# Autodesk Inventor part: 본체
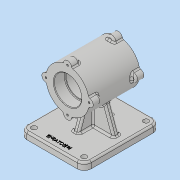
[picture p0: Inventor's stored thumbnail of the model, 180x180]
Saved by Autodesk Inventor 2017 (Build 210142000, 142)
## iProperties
Part Number: 본체
Material: 일반
Document SubType Name: Modeling
Designer: MRC
Density: 1 g/cm^3
Appearance: 기본값
Author: MRC
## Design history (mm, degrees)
sketch "스케치1"
  geometry: L1 (0, 0)-(0, 43.5); L2 (37, 43.5)-(23.5, 43.5); L3 (23.5, 43.5)-(23.5, 24.5); L4 (23.5, 24.5)-(21, 24.5); L5 (21, 24.5)-(21, 0); L6 (21, 0)-(37, 0); L7 (37, 0)-(37, 43.5)
  constraints: 14 end point, 5 perpendicular, 2 horizontal alignment, 1 horizontal, 1 vertical
  dimensions: "d0" = 43.5 distance of L1.start L1.end; "d1" = 47 diameter of L3 L1; "d2" = 42 diameter of L5 L1; "d3" = 74 diameter of L7 L1; "d4" = 19 distance of L2.end L3.end
revolve "회전1" sketch "스케치1" stored, may be unused: angle "d5" = 90 deg
sketch "스케치2"
  geometry: C1 r 7 at (0, 37); 2 further points
  constraints: 2 vertical alignment, 1 centre point, 1 other
  dimensions: "d6" = 14 diameter of C1
extrude "돌출1" join sketch "스케치2" distance "d7" = 14; taper "d8" = 0 deg
sketch "스케치3"
  geometry: A1 r 7 centre (0, 0) between (6.969, -0.662) and (-6.969, -0.662) reference; 2 further points
  constraints: 1 coincident
hole "구멍1" sketch "스케치3" at (0, 0) diameter "d9" = 3.242; stored, may be unused: countersink angle "d13" = 90 deg, drill point angle "d15" = 118 deg; dims "d10" = 8, "d11" = 4, "d12" = 2, "d14" = 10
chamfer "모따기1" distance "d20" = 1; stored, may be unused: second distance "d21" = 2, angle "d22" = 45 deg
fillet "모깎기1" dims "d19" = 1
fillet "모깎기2" dims "d23" = 3
fillet "모깎기3" dims "d24" = 3
node "작업 평면1"
sketch "스케치4"
  geometry: L1 (55, 70)-(-55, 70); L2 (-55, 70)-(-55, -60); L3 (-55, -60)-(55, -60); L4 (55, -60)-(55, 70); 2 further points
  constraints: 8 end point, 2 parallel, 1 horizontal, 1 midpoint, 1 perpendicular, 1 vertical alignment
  dimensions: "d26" = 130 distance of L1.end L2.end; "d27" = 110 distance of L2.end L3.end; "d28" = 70 distance from line of point (0, 0) L1
extrude "돌출2" join sketch "스케치4" distance "d29" = 12; taper "d30" = 0 deg
fillet "모깎기4" dims "d31" = 12
sketch "스케치5"
  geometry: C1 r 4.5 at (43, -58); C2 r 4.5 at (43, 48); C3 r 4.5 at (-43, 48); C4 r 4.5 at (-43, -58); A1 r 12 centre (43, -58) between (43, -70) and (55, -58) reference; A2 r 12 centre (-43, -58) between (-55, -58) and (-43, -70) reference; A3 r 12 centre (-43, 48) between (-43, 60) and (-55, 48) reference; A4 r 12 centre (43, 48) between (55, 48) and (43, 60) reference; 1 further point
  constraints: 4 centre point, 4 concentric, 3 equal radius
  dimensions: "d32" = 9 diameter of C1
extrude "돌출3" cut sketch "스케치5" stored distance "d33" = 12; taper "d34" = 0 deg
sketch "스케치6"
  geometry: L1 (-5, -5)-(5, -5); L2 (5, -5)-(5, 5); L3 (5, 5)-(-5, 5); L4 (-5, 5)-(-5, -5); L5 (-5, -5)-(5, 5); L6 (5, -5)-(-5, 5); 1 further point
  constraints: 12 end point, 2 midpoint, 2 parallel, 1 horizontal, 1 perpendicular
  dimensions: "d41" = 10 distance of L3.end L2.end; "d42" = 10 distance of L2.end L1.end
extrude "돌출4" join sketch "스케치6" stored distance "d43" = 12; taper "d44" = 0 deg
sketch "스케치7"
  geometry: L1 (41, -70)-(34.428, -51.943); L2 (43, -70)-(55, -70) reference; L3 (55, -70)-(55, -82) reference; 1 further point
  constraints: 2 end point, 1 point on line
  dimensions: "d45" = 14 distance from line of L1.start L3; "d46" = 110 deg angle of L1 L2
feature "리브1" sketch "스케치7" dims "d47" = 1, "d48" = 10, "d49" = 0, "d50" = 0, "d51" = 1, "d52" = 1
sketch "스케치8"
  geometry: L1 (-70, -30)-(-60.218, -26.44); L2 (-70, -48)-(-70, 58) reference; 1 further point
  constraints: 2 end point, 1 point on line
  dimensions: "d53" = 30 vertical distance of L1.start point (0, 0); "d54" = 110 deg angle of L1 L2
feature "리브2" sketch "스케치8" dims "d55" = 1, "d56" = 10, "d57" = 0, "d58" = 0, "d59" = 1, "d60" = 1
fillet "모깎기5" dims "d64" = 3
fillet "모깎기6" dims "d65" = 3
sketch "스케치9"
  geometry: 2 further points
  constraints: 1 vertical alignment, 1 other
  dimensions: "d61" = 58 distance of point (0, -58) point (0, 0)
feature "엠보싱2" sketch "스케치9" dims "d0" = 43.5, "d1" = 47, "d2" = 42, "d3" = 74, "d4" = 19, "d10" = 8, "d66" = 0.5, "d67" = 0
node "솔리드1"
pattern_circular "원형 패턴1" dims angle "d17" = 360 deg
mirror "미러1"
mirror "미러2"
mirror "미러3"
other parameters: "d25" = -82
